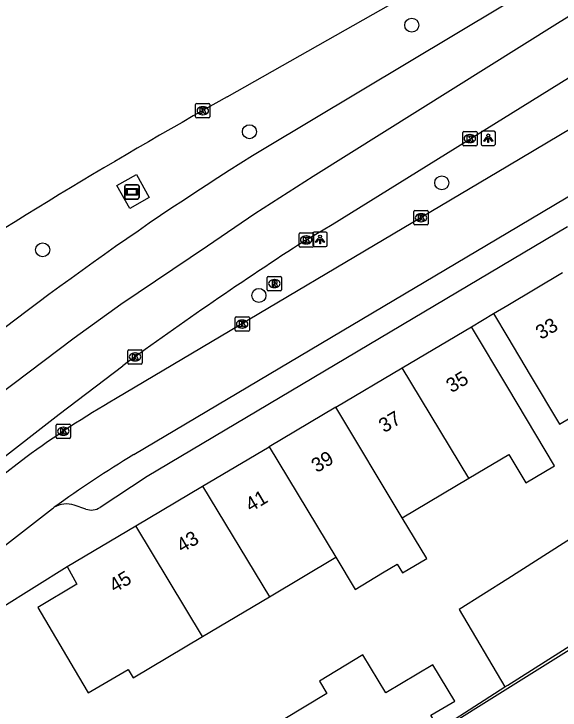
# Model space of a CAD drawing. Extents: x 160107 to 160928, y 382056 to 382918.
# Drawn here: x 160465.57 to 160503.65, y 382624.26 to 382672.83 of the extents above; entities that cross this region are included whole.
import ezdxf

# ---------------------------------------------------------------- set-up
doc = ezdxf.new("R2010")
doc.units = 0
for name, color, linetype in [('IMGEO_Berm_groen', 7, 'Continuous'), ('IMGEO_Boom', 7, 'Continuous'), ('IMGEO_Kolk', 7, 'Continuous'), ('IMGEO_Lichtpunt', 7, 'Continuous'), ('IMGEO_Muur', 7, 'Continuous'), ('IMGEO_Pand', 7, 'Continuous'), ('IMGEO_Pand_nummerreeks', 7, 'Continuous'), ('IMGEO_Reclamebord', 7, 'Continuous'), ('IMGEO_Rijbaan_lokaal_gesloten', 7, 'Continuous'), ('IMGEO_Rijbaan_lokaal_open', 7, 'Continuous'), ('IMGEO_Rioolput', 7, 'Continuous'), ('IMGEO_Voetpad_open', 7, 'Continuous')]:
    doc.layers.add(name, color=color, linetype=linetype)

msp = doc.modelspace()

# ---------------------------------------------------------------- linework, layer by layer
at = {"layer": 'IMGEO_Berm_groen'}
msp.add_lwpolyline([(160472.74, 382660.86), (160474.11, 382661.628), (160475.007, 382660.028), (160473.637, 382659.26), (160472.74, 382660.86)], dxfattribs=at)
at = {"layer": 'IMGEO_Boom'}
for centre in [(160493.306, 382672.04), (160481.989, 382664.609), (160495.4, 382661.043), (160467.569, 382656.365), (160482.649, 382653.188)]:
    msp.add_circle(centre, 0.489, dxfattribs=at)
at = {"layer": 'IMGEO_Kolk'}
for p, q in [((160478.234, 382665.65), (160478.234, 382666.502)), ((160478.309, 382666.576), (160479.161, 382666.576)), ((160478.722, 382666.356), (160478.747, 382666.356)), ((160479.235, 382666.502), (160479.235, 382665.65)), ((160478.745, 382665.796), (160478.72, 382665.796)), ((160479.161, 382665.576), (160478.309, 382665.576)), ((160496.861, 382663.701), (160496.861, 382664.553)), ((160496.936, 382664.627), (160497.788, 382664.627)), ((160497.349, 382664.407), (160497.374, 382664.407)), ((160497.862, 382664.553), (160497.862, 382663.701)), ((160497.372, 382663.847), (160497.347, 382663.847)), ((160497.788, 382663.627), (160496.936, 382663.627)), ((160493.456, 382658.18), (160493.456, 382659.032)), ((160493.531, 382659.106), (160494.383, 382659.106)), ((160494.457, 382659.032), (160494.457, 382658.18)), ((160493.944, 382658.886), (160493.969, 382658.886)), ((160494.383, 382658.106), (160493.531, 382658.106)), ((160493.967, 382658.326), (160493.942, 382658.326)), ((160485.522, 382657.559), (160486.374, 382657.559)), ((160485.447, 382656.633), (160485.447, 382657.485)), ((160485.935, 382657.339), (160485.96, 382657.339)), ((160486.448, 382657.485), (160486.448, 382656.633)), ((160486.374, 382656.559), (160485.522, 382656.559)), ((160485.958, 382656.779), (160485.933, 382656.779)), ((160481.06, 382651.69), (160481.912, 382651.69)), ((160480.985, 382650.764), (160480.985, 382651.616)), ((160481.473, 382651.47), (160481.498, 382651.47)), ((160481.986, 382651.616), (160481.986, 382650.764)), ((160481.496, 382650.91), (160481.471, 382650.91)), ((160481.912, 382650.69), (160481.06, 382650.69)), ((160473.51, 382648.473), (160473.51, 382649.325)), ((160473.585, 382649.399), (160474.437, 382649.399)), ((160474.511, 382649.325), (160474.511, 382648.473)), ((160473.998, 382649.179), (160474.023, 382649.179)), ((160474.437, 382648.399), (160473.585, 382648.399)), ((160474.021, 382648.619), (160473.996, 382648.619)), ((160468.51, 382643.287), (160468.51, 382644.139)), ((160468.585, 382644.213), (160469.437, 382644.213)), ((160468.998, 382643.993), (160469.023, 382643.993)), ((160469.511, 382644.139), (160469.511, 382643.287)), ((160469.021, 382643.433), (160468.996, 382643.433)), ((160469.437, 382643.213), (160468.585, 382643.213))]:
    msp.add_line(p, q, dxfattribs=at)
for points in [[(160478.234, 382665.65), (160478.234, 382666.502)], [(160478.309, 382666.576), (160479.161, 382666.576)], [(160478.555, 382666.276), (160478.678, 382666.276), (160478.678, 382666.125), (160478.808, 382666.276), (160478.972, 382666.276), (160478.826, 382666.125), (160478.979, 382665.876), (160478.827, 382665.876), (160478.742, 382666.04), (160478.678, 382665.973), (160478.678, 382665.876), (160478.555, 382665.876), (160478.555, 382666.276)], [(160479.235, 382666.502), (160479.235, 382665.65)], [(160479.161, 382665.576), (160478.309, 382665.576)], [(160496.861, 382663.701), (160496.861, 382664.553)], [(160496.936, 382664.627), (160497.788, 382664.627)], [(160497.182, 382664.327), (160497.305, 382664.327), (160497.305, 382664.176), (160497.435, 382664.327), (160497.599, 382664.327), (160497.453, 382664.176), (160497.606, 382663.927), (160497.454, 382663.927), (160497.369, 382664.091), (160497.305, 382664.024), (160497.305, 382663.927), (160497.182, 382663.927), (160497.182, 382664.327)], [(160497.862, 382664.553), (160497.862, 382663.701)], [(160497.788, 382663.627), (160496.936, 382663.627)], [(160493.456, 382658.18), (160493.456, 382659.032)], [(160493.531, 382659.106), (160494.383, 382659.106)], [(160494.457, 382659.032), (160494.457, 382658.18)], [(160493.777, 382658.806), (160493.9, 382658.806), (160493.9, 382658.655), (160494.03, 382658.806), (160494.194, 382658.806), (160494.048, 382658.655), (160494.201, 382658.406), (160494.049, 382658.406), (160493.964, 382658.57), (160493.9, 382658.503), (160493.9, 382658.406), (160493.777, 382658.406), (160493.777, 382658.806)], [(160494.383, 382658.106), (160493.531, 382658.106)], [(160485.522, 382657.559), (160486.374, 382657.559)], [(160485.447, 382656.633), (160485.447, 382657.485)], [(160485.768, 382657.259), (160485.891, 382657.259), (160485.891, 382657.108), (160486.021, 382657.259), (160486.185, 382657.259), (160486.039, 382657.108), (160486.192, 382656.859), (160486.04, 382656.859), (160485.955, 382657.023), (160485.891, 382656.956), (160485.891, 382656.859), (160485.768, 382656.859), (160485.768, 382657.259)], [(160486.448, 382657.485), (160486.448, 382656.633)], [(160486.374, 382656.559), (160485.522, 382656.559)], [(160481.06, 382651.69), (160481.912, 382651.69)], [(160480.985, 382650.764), (160480.985, 382651.616)], [(160481.306, 382651.39), (160481.429, 382651.39), (160481.429, 382651.239), (160481.559, 382651.39), (160481.723, 382651.39), (160481.577, 382651.239), (160481.73, 382650.99), (160481.578, 382650.99), (160481.493, 382651.154), (160481.429, 382651.087), (160481.429, 382650.99), (160481.306, 382650.99), (160481.306, 382651.39)], [(160481.986, 382651.616), (160481.986, 382650.764)], [(160481.912, 382650.69), (160481.06, 382650.69)], [(160473.51, 382648.473), (160473.51, 382649.325)], [(160473.585, 382649.399), (160474.437, 382649.399)], [(160474.511, 382649.325), (160474.511, 382648.473)], [(160473.831, 382649.099), (160473.954, 382649.099), (160473.954, 382648.948), (160474.084, 382649.099), (160474.248, 382649.099), (160474.102, 382648.948), (160474.255, 382648.699), (160474.103, 382648.699), (160474.018, 382648.863), (160473.954, 382648.796), (160473.954, 382648.699), (160473.831, 382648.699), (160473.831, 382649.099)], [(160474.437, 382648.399), (160473.585, 382648.399)], [(160468.51, 382643.287), (160468.51, 382644.139)], [(160468.585, 382644.213), (160469.437, 382644.213)], [(160468.831, 382643.913), (160468.954, 382643.913), (160468.954, 382643.762), (160469.084, 382643.913), (160469.248, 382643.913), (160469.102, 382643.762), (160469.255, 382643.513), (160469.103, 382643.513), (160469.018, 382643.677), (160468.954, 382643.61), (160468.954, 382643.513), (160468.831, 382643.513), (160468.831, 382643.913)], [(160469.511, 382644.139), (160469.511, 382643.287)], [(160469.437, 382643.213), (160468.585, 382643.213)]]:
    msp.add_lwpolyline(points, dxfattribs=at)
for centre, start, end in [((160478.311, 382666.5), 91.552, 178.448), ((160478.311, 382666.5), 91.552, 178.448), ((160479.159, 382666.5), 1.552, 88.448), ((160479.159, 382666.5), 1.552, 88.448), ((160478.311, 382665.652), 181.552, 268.448), ((160478.311, 382665.652), 181.552, 268.448), ((160479.159, 382665.652), 271.552, 358.448), ((160479.159, 382665.652), 271.552, 358.448), ((160496.938, 382664.551), 91.552, 178.448), ((160496.938, 382664.551), 91.552, 178.448), ((160497.786, 382664.551), 1.552, 88.448), ((160497.786, 382664.551), 1.552, 88.448), ((160496.938, 382663.703), 181.552, 268.448), ((160496.938, 382663.703), 181.552, 268.448), ((160497.786, 382663.703), 271.552, 358.448), ((160497.786, 382663.703), 271.552, 358.448), ((160493.533, 382659.03), 91.552, 178.448), ((160493.533, 382659.03), 91.552, 178.448), ((160494.381, 382659.03), 1.552, 88.448), ((160494.381, 382659.03), 1.552, 88.448), ((160493.533, 382658.182), 181.552, 268.448), ((160493.533, 382658.182), 181.552, 268.448), ((160494.381, 382658.182), 271.552, 358.448), ((160494.381, 382658.182), 271.552, 358.448), ((160485.524, 382657.483), 91.552, 178.448), ((160485.524, 382657.483), 91.552, 178.448), ((160486.372, 382657.483), 1.552, 88.448), ((160486.372, 382657.483), 1.552, 88.448), ((160485.524, 382656.635), 181.552, 268.448), ((160485.524, 382656.635), 181.552, 268.448), ((160486.372, 382656.635), 271.552, 358.448), ((160486.372, 382656.635), 271.552, 358.448), ((160481.062, 382651.614), 91.552, 178.448), ((160481.062, 382651.614), 91.552, 178.448), ((160481.91, 382651.614), 1.552, 88.448), ((160481.91, 382651.614), 1.552, 88.448), ((160481.062, 382650.766), 181.552, 268.448), ((160481.062, 382650.766), 181.552, 268.448), ((160481.91, 382650.766), 271.552, 358.448), ((160481.91, 382650.766), 271.552, 358.448), ((160473.587, 382649.323), 91.552, 178.448), ((160473.587, 382649.323), 91.552, 178.448), ((160474.435, 382649.323), 1.552, 88.448), ((160474.435, 382649.323), 1.552, 88.448), ((160473.587, 382648.475), 181.552, 268.448), ((160473.587, 382648.475), 181.552, 268.448), ((160474.435, 382648.475), 271.552, 358.448), ((160474.435, 382648.475), 271.552, 358.448), ((160468.587, 382644.137), 91.552, 178.448), ((160468.587, 382644.137), 91.552, 178.448), ((160469.435, 382644.137), 1.552, 88.448), ((160469.435, 382644.137), 1.552, 88.448), ((160468.587, 382643.289), 181.552, 268.448), ((160468.587, 382643.289), 181.552, 268.448), ((160469.435, 382643.289), 271.552, 358.448), ((160469.435, 382643.289), 271.552, 358.448)]:
    msp.add_arc(centre, 0.0765, start, end, dxfattribs=at)
for centre, major_axis, ratio, start_param, end_param in [((160478.721, 382666.076), (-0.387, 0.002), 0.722429, 4.712389, 7.853982), ((160478.746, 382666.076), (-0.39, 0.002), 0.717154, 1.570796, 4.712389), ((160497.348, 382664.127), (-0.387, 0.002), 0.722429, 4.712389, 7.853982), ((160497.373, 382664.127), (-0.39, 0.002), 0.717154, 1.570796, 4.712389), ((160493.943, 382658.606), (-0.387, 0.002), 0.722429, 4.712389, 7.853982), ((160493.968, 382658.606), (-0.39, 0.002), 0.717154, 1.570796, 4.712389), ((160485.934, 382657.059), (-0.387, 0.002), 0.722429, 4.712389, 7.853982), ((160485.959, 382657.059), (-0.39, 0.002), 0.717154, 1.570796, 4.712389), ((160481.472, 382651.19), (-0.387, 0.002), 0.722429, 4.712389, 7.853982), ((160481.497, 382651.19), (-0.39, 0.002), 0.717154, 1.570796, 4.712389), ((160473.997, 382648.899), (-0.387, 0.002), 0.722429, 4.712389, 7.853982), ((160474.022, 382648.899), (-0.39, 0.002), 0.717154, 1.570796, 4.712389), ((160468.997, 382643.713), (-0.387, 0.002), 0.722429, 4.712389, 7.853982), ((160469.022, 382643.713), (-0.39, 0.002), 0.717154, 1.570796, 4.712389)]:
    msp.add_ellipse(centre, major_axis=major_axis, ratio=ratio, start_param=start_param, end_param=end_param, dxfattribs=at)
at = {"layer": 'IMGEO_Lichtpunt'}
for p, q in [((160498.145, 382664.557), (160498.145, 382663.75)), ((160498.145, 382664.557), (160498.145, 382663.75)), ((160499.047, 382664.652), (160498.239, 382664.652)), ((160499.047, 382664.652), (160498.239, 382664.652)), ((160499.141, 382663.75), (160499.141, 382664.557)), ((160499.141, 382663.75), (160499.141, 382664.557)), ((160498.239, 382663.656), (160499.047, 382663.656)), ((160498.239, 382663.656), (160499.047, 382663.656)), ((160486.415, 382657.5), (160486.415, 382656.693)), ((160486.415, 382657.5), (160486.415, 382656.693)), ((160487.317, 382657.595), (160486.509, 382657.595)), ((160487.317, 382657.595), (160486.509, 382657.595)), ((160487.411, 382656.693), (160487.411, 382657.5)), ((160487.411, 382656.693), (160487.411, 382657.5)), ((160486.509, 382656.599), (160487.317, 382656.599)), ((160486.509, 382656.599), (160487.317, 382656.599))]:
    msp.add_line(p, q, dxfattribs=at)
for points in [[(160498.519, 382664.221), (160498.558, 382664.193), (160498.37, 382663.931), (160498.332, 382663.958), (160498.519, 382664.221)], [(160498.621, 382664.173), (160498.668, 382664.173), (160498.668, 382663.851), (160498.621, 382663.851), (160498.621, 382664.173)], [(160498.731, 382664.193), (160498.769, 382664.22), (160498.956, 382663.958), (160498.917, 382663.93), (160498.731, 382664.193)], [(160486.789, 382657.164), (160486.828, 382657.136), (160486.64, 382656.874), (160486.602, 382656.901), (160486.789, 382657.164)], [(160486.891, 382657.116), (160486.938, 382657.116), (160486.938, 382656.794), (160486.891, 382656.794), (160486.891, 382657.116)], [(160487.001, 382657.136), (160487.039, 382657.163), (160487.226, 382656.901), (160487.187, 382656.873), (160487.001, 382657.136)]]:
    msp.add_lwpolyline(points, dxfattribs=at)
for centre in [(160498.644, 382664.355), (160486.914, 382657.298)]:
    msp.add_circle(centre, 0.0994, dxfattribs=at)
for centre, start, end in [((160498.239, 382664.557), 90, 180), ((160498.239, 382664.557), 90, 180), ((160499.047, 382664.557), 0, 90), ((160499.047, 382664.557), 0, 90), ((160498.239, 382663.75), 180, 270), ((160498.239, 382663.75), 180, 270), ((160499.047, 382663.75), 270, 0), ((160499.047, 382663.75), 270, 360), ((160486.509, 382657.5), 90, 180), ((160486.509, 382657.5), 90, 180), ((160487.317, 382657.5), 0, 90), ((160487.317, 382657.5), 0, 90), ((160486.509, 382656.693), 180, 270), ((160486.509, 382656.693), 180, 270), ((160487.317, 382656.693), 270, 0), ((160487.317, 382656.693), 270, 360)]:
    msp.add_arc(centre, 0.0946, start, end, dxfattribs=at)
at = {"layer": 'IMGEO_Muur'}
msp.add_lwpolyline([(160495.212, 382622.935), (160499.797, 382625.871)], dxfattribs=at)
at = {"layer": 'IMGEO_Pand'}
for points in [[(160499.009, 382651.916), (160500, 382652.505), (160503.822, 382654.776)], [(160499.009, 382651.916), (160500, 382650.257), (160501.573, 382647.624), (160503.61, 382644.212), (160508.424, 382647.072)], [(160492.65, 382648.134), (160497.472, 382650.994)], [(160497.287, 382640.428), (160500.082, 382642.089), (160501.265, 382640.109), (160503.264, 382641.304), (160500, 382646.765), (160497.472, 382650.994)], [(160488.006, 382645.38), (160492.65, 382648.134)], [(160497.287, 382640.428), (160492.65, 382648.134)], [(160488.006, 382645.38), (160483.355, 382642.622)], [(160492.646, 382637.67), (160488.006, 382645.38)], [(160478.711, 382639.868), (160483.355, 382642.622)], [(160483.355, 382642.622), (160488.017, 382634.919)], [(160492.646, 382637.67), (160497.287, 382640.428)], [(160474.061, 382637.109), (160478.711, 382639.868)], [(160478.711, 382639.868), (160483.383, 382632.165)], [(160488.017, 382634.919), (160489.372, 382632.68), (160491.265, 382633.825), (160492.293, 382634.447), (160492.669, 382633.824), (160494.349, 382634.841), (160492.646, 382637.67)], [(160469.27, 382634.268), (160474.061, 382637.109)], [(160478.723, 382629.396), (160474.061, 382637.109)], [(160499.797, 382625.871), (160500, 382626), (160509.035, 382631.728), (160505.794, 382637.101), (160500, 382633.42), (160496.616, 382631.27), (160499.797, 382625.871)], [(160483.383, 382632.165), (160488.017, 382634.919)], [(160469.27, 382634.268), (160469.96, 382633.039), (160467.23, 382631.423), (160469.766, 382627.114), (160470.743, 382625.454), (160473.536, 382627.098), (160473.882, 382626.519), (160478.723, 382629.396)], [(160478.723, 382629.396), (160483.383, 382632.165)], [(160477.432, 382615.94), (160479.664, 382613.615), (160482.477, 382615.301), (160485.968, 382617.393), (160485.379, 382618.374), (160486.928, 382619.257), (160487.511, 382618.286), (160495.212, 382622.935), (160494.641, 382623.899), (160496.306, 382624.888), (160494.782, 382627.419), (160491.499, 382625.469), (160489.904, 382628.108), (160486.865, 382626.272), (160487.382, 382625.416), (160484.334, 382623.575), (160485.332, 382621.923), (160483.791, 382620.991), (160482.792, 382622.642), (160479.292, 382620.529), (160475.509, 382618.245)]]:
    msp.add_lwpolyline(points, dxfattribs=at)
at = {"layer": 'IMGEO_Reclamebord'}
for p, q in [((160473.398, 382660.911), (160474.188, 382660.911)), ((160474.188, 382660.911), (160473.398, 382660.911)), ((160473.298, 382660.011), (160473.298, 382660.811)), ((160473.298, 382660.811), (160473.298, 382660.011)), ((160474.288, 382660.811), (160474.288, 382660.011)), ((160474.288, 382660.011), (160474.288, 382660.811)), ((160474.188, 382659.911), (160473.398, 382659.911)), ((160473.398, 382659.911), (160474.188, 382659.911))]:
    msp.add_line(p, q, dxfattribs=at)
for points in [[(160473.399, 382660.643), (160474.187, 382660.643), (160474.187, 382660.179), (160473.399, 382660.179), (160473.399, 382660.643)], [(160473.464, 382660.578), (160473.464, 382660.244), (160474.122, 382660.244), (160474.122, 382660.578), (160473.464, 382660.578)]]:
    msp.add_lwpolyline(points, dxfattribs=at)
for centre, start, end in [((160473.398, 382660.811), 90, 180), ((160473.398, 382660.811), 90, 180), ((160474.188, 382660.811), 0, 90), ((160474.188, 382660.811), 360, 90), ((160473.398, 382660.011), 180, 270), ((160473.398, 382660.011), 180, 270), ((160474.188, 382660.011), 270, 0), ((160474.188, 382660.011), 270, 0)]:
    msp.add_arc(centre, 0.1, start, end, dxfattribs=at)
at = {"layer": 'IMGEO_Rijbaan_lokaal_gesloten'}
for points in [[(160480.438, 382667.032), (160493.08, 382674.223), (160495.895, 382675.755), (160504.575, 382680.884), (160517.652, 382689.261)], [(160517.886, 382681.055), (160503.477, 382672.156), (160486.426, 382661.475), (160482.364, 382658.869), (160479.058, 382656.635), (160473.015, 382652.551), (160469.77, 382650.215), (160463.375, 382645.381), (160460.241, 382642.817), (160454.145, 382637.554), (160450.613, 382634.314), (160445.366, 382629.28), (160442.543, 382626.393), (160435.829, 382618.957)], [(160514.82, 382680.24), (160511.153, 382680.151), (160509.661, 382679.382), (160483.011, 382663.422)], [(160485.875, 382657.016), (160487.76, 382658.143), (160522.93, 382680.002)], [(160453.273, 382632.058), (160454.689, 382633.387), (160457.061, 382635.451), (160459.656, 382637.803), (160464.193, 382641.393), (160468.729, 382644.914), (160473.164, 382648.285)]]:
    msp.add_lwpolyline(points, dxfattribs=at)
for centre, radius, start, end in [((160655.439, 382352.804), 359.673, 119.11441, 123.71784), ((160597.122, 382479.023), 216.851, 121.75023, 137.88092), ((160632.509, 382429.921), 270.322, 122.85014, 126.11907)]:
    msp.add_arc(centre, radius, start, end, dxfattribs=at)
at = {"layer": 'IMGEO_Rijbaan_lokaal_open'}
for points in [[(160507.171, 382666.461), (160506.389, 382665.994), (160500, 382662.216), (160472.648, 382645.963)], [(160473.921, 382642.082), (160500, 382657.577), (160505.676, 382660.95), (160506.309, 382661.21), (160507.255, 382661.292)], [(160466.399, 382641.882), (160460.573, 382637.412)], [(160462.535, 382633.912), (160462.785, 382634.09), (160468.262, 382638.324), (160468.318, 382638.364), (160468.374, 382638.405)], [(160525.477, 382626.898), (160516.443, 382636.034), (160510.687, 382632.435), (160500, 382625.753), (160480.01, 382613.255), (160480.277, 382612.822), (160464.977, 382593.454)]]:
    msp.add_lwpolyline(points, dxfattribs=at)
for centre, radius, start, end in [((160505.57, 382588.727), 66.029, 119.90721, 126.38704), ((160519.821, 382566.816), 88.158, 121.3765, 125.70277)]:
    msp.add_arc(centre, radius, start, end, dxfattribs=at)
at = {"layer": 'IMGEO_Rioolput'}
for p, q in [((160483.228, 382653.588), (160483.228, 382654.44)), ((160483.303, 382654.514), (160484.155, 382654.514)), ((160483.716, 382654.294), (160483.741, 382654.294)), ((160484.229, 382654.44), (160484.229, 382653.588)), ((160483.739, 382653.734), (160483.714, 382653.734)), ((160484.155, 382653.514), (160483.303, 382653.514))]:
    msp.add_line(p, q, dxfattribs=at)
for points in [[(160483.228, 382653.588), (160483.228, 382654.44)], [(160483.303, 382654.514), (160484.155, 382654.514)], [(160483.817, 382654.212), (160483.565, 382654.214), (160483.565, 382653.814)], [(160483.743, 382654.133), (160483.689, 382654.133), (160483.689, 382654.052)], [(160484.229, 382654.44), (160484.229, 382653.588)], [(160483.565, 382653.814), (160483.689, 382653.814), (160483.689, 382653.976), (160483.7, 382653.976)], [(160483.689, 382654.052), (160483.741, 382654.052)], [(160483.747, 382653.947), (160483.818, 382653.814), (160483.958, 382653.814), (160483.893, 382653.94)], [(160484.155, 382653.514), (160483.303, 382653.514)]]:
    msp.add_lwpolyline(points, dxfattribs=at)
for centre, radius, start, end in [((160483.305, 382654.438), 0.0765, 91.552, 178.448), ((160483.305, 382654.438), 0.0765, 91.552, 178.448), ((160483.749, 382654.037), 0.0964, 77.0061, 93.1865), ((160483.763, 382654.094), 0.0378, 276.6634, 79.6772), ((160483.816, 382654.102), 0.109, 350.3612, 89.416), ((160484.153, 382654.438), 0.0765, 1.552, 88.448), ((160484.153, 382654.438), 0.0765, 1.552, 88.448), ((160483.699, 382653.923), 0.0533, 26.0293, 88.6989), ((160483.725, 382654.241), 0.19, 274.7715, 282.9687), ((160483.814, 382654.102), 0.112, 277.5842, 350.9817), ((160483.798, 382653.887), 0.108, 29.5134, 73.7905), ((160483.305, 382653.59), 0.0765, 181.552, 268.448), ((160483.305, 382653.59), 0.0765, 181.552, 268.448), ((160484.153, 382653.59), 0.0765, 271.552, 358.448), ((160484.153, 382653.59), 0.0765, 271.552, 358.448)]:
    msp.add_arc(centre, radius, start, end, dxfattribs=at)
for centre, major_axis, ratio, start_param, end_param in [((160483.715, 382654.014), (-0.387, 0.002), 0.722429, 4.712389, 7.853982), ((160483.74, 382654.014), (-0.39, 0.002), 0.717154, 1.570796, 4.712389)]:
    msp.add_ellipse(centre, major_axis=major_axis, ratio=ratio, start_param=start_param, end_param=end_param, dxfattribs=at)
at = {"layer": 'IMGEO_Voetpad_open'}
for points in [[(160504.163, 382657.966), (160474.868, 382640.552), (160471.576, 382638.402)], [(160497.472, 382650.994), (160499.009, 382651.916)], [(160470.583, 382638.278), (160469.771, 382638.557)], [(160464.675, 382631.392), (160469.27, 382634.268)]]:
    msp.add_lwpolyline(points, dxfattribs=at)
for centre, radius, start, end in [((160469.238, 382636.963), 1.681, 71.5021, 120.9171), ((160470.953, 382639.354), 1.138, 251.0322, 303.2036)]:
    msp.add_arc(centre, radius, start, end, dxfattribs=at)

# ---------------------------------------------------------------- texts
at = {"layer": 'IMGEO_Pand_nummerreeks'}
for s, rotation, p in [('33', 30.7155, (160502.324, 382650.07)), ('35', 30.6713, (160496.084, 382646.357)), ('37', 30.6713, (160491.384, 382643.569)), ('39', 30.6704, (160486.683, 382640.783)), ('41', 30.6713, (160482.08, 382638.052)), ('43', 30.6713, (160477.283, 382635.206)), ('45', 30.6713, (160472.582, 382632.419))]:
    msp.add_text(s, height=1, rotation=rotation, dxfattribs=at).set_placement(p)

doc.saveas('drawing.dxf')
